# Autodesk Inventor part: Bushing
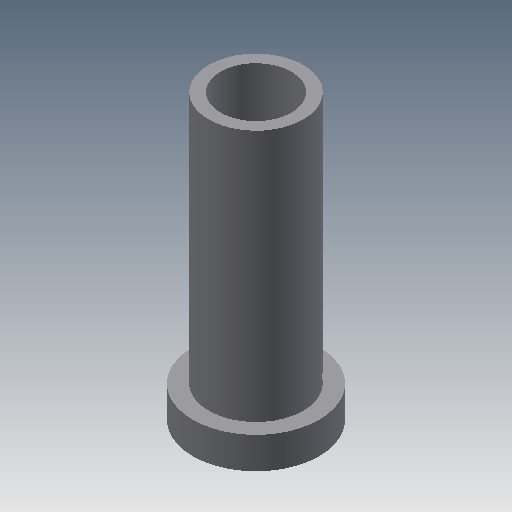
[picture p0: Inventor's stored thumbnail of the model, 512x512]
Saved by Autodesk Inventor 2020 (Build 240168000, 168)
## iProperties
Created: 2002-02
Part Number: Bushing
Document SubType Name: Modeling
Designer: ***
Density: 1 g/cm^3
Material: Generic
Appearance: Default
Control State: 0
Master: False
Checked Out: False
Shininess: 77.0
Length Units: 11269
Angle Units: 11279
Time Units: 11290
Mass Units: 11283
Length Display Precision: 3
Angle Display Precision: 2
Density: 0.0
Volumn: 0.0
Area: 0.0
PropertySet Name: Model Information
Author: ***
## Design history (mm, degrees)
sketch "Sketch1"
  geometry: L1 (6.25, 50.44)-(6.25, 5.44); L2 (6.25, 5.44)-(10.625, 5.44); L3 (10.625, 5.44)-(10.625, 10.44); L4 (10.625, 10.44)-(8.125, 10.44); L5 (8.125, 10.44)-(8.125, 50.44); L6 (8.125, 50.44)-(6.25, 50.44); L7 (0.625, 34.884)-(0.625, 0)
  constraints: 14 end point, 4 parallel, 2 perpendicular, 1 vertical
  dimensions: "d0" = 20 diameter of L3 L7; "d1" = 11.25 diameter of L1 L7; "d2" = 15 diameter of L5 L7; "d4" = 5 distance of L2.end L3.end; "d5" = 45 distance of L1.start L1.end
revolve "Revolution1" sketch "Sketch1" stored, may be unused: angle "d3" = 90 deg
body "Solid1"
